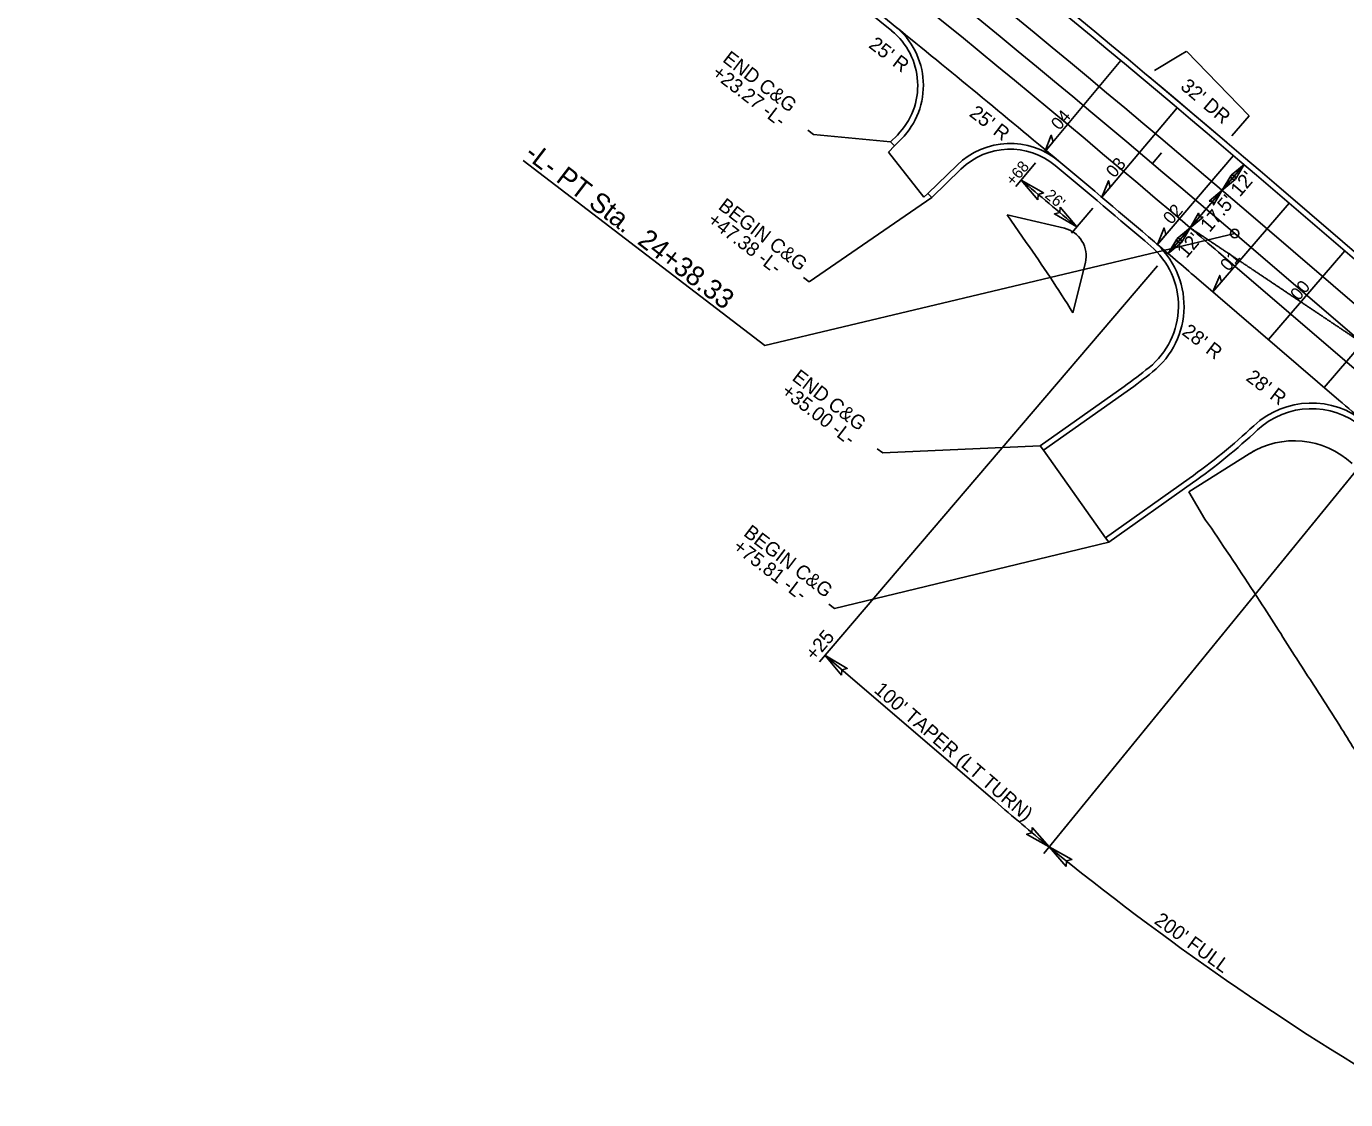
# Model space of a CAD drawing. Extents: x 1616561 to 1622460, y 896726 to 899651.
# Drawn here: x 1618799.1 to 1619267.2, y 897970.3 to 898351.2 of the extents above; entities that cross this region are included whole.
import ezdxf

# ---------------------------------------------------------------- set-up
doc = ezdxf.new("R2010")
doc.units = 0
for name, color, linetype in [('Old_Level_3', 7, 'Continuous'), ('Prop Conc Drive Radius Type', 7, 'Continuous'), ('Prop Dimension', 7, 'Continuous'), ('Prop DSN Text', 7, 'Continuous'), ('Prop Horizontal Alignment Tick Small', 7, 'Continuous'), ('Prop North Arrow NAD83 for Plan Sheets CELL', 7, 'Continuous'), ('Prop Rem of Exist Asph Pvmt', 7, 'Continuous'), ('Prop Superelevation  Arrow CELL', 7, 'Continuous'), ('Prop Terminator CELL', 7, 'Continuous'), ('Sheet Cutting Line CELL', 7, 'Continuous'), ('Sheet North Arrow CELL', 7, 'Continuous'), ('Sheet Sticker Preliminary CELL', 7, 'Continuous')]:
    doc.layers.add(name, color=color, linetype=linetype)

msp = doc.modelspace()

# ---------------------------------------------------------------- linework, layer by layer
at = {"layer": 'Old_Level_3'}
for p, q in [((1619233.52, 898284.32), (1619284.05, 898240.93)), ((1619222.12, 898271.04), (1619272.65, 898227.65)), ((1619214.3, 898261.93), (1619264.83, 898218.55))]:
    msp.add_line(p, q, dxfattribs=at)
for centre, radius, start, end in [((1615970.53, 894484.25), 5008.75, 49.34838, 55.47944), ((1615970.53, 894484.25), 4991.25, 49.50113, 55.47944), ((1615970.53, 894484.25), 4979.25, 50.08506, 50.95117), ((1615970.53, 894484.25), 4991.25, 49.34838, 49.50113), ((1615970.53, 894484.25), 4979.25, 49.34838, 49.57531), ((1619799.51, 898841.24), 820.75, 229.34838, 230.21163)]:
    msp.add_arc(centre, radius, start, end, dxfattribs=at)
for points in [[(1619253.85, 898251.7), (1619253.29, 898252.08), (1619252.72, 898252.46), (1619252.16, 898252.84), (1619251.59, 898253.22), (1619251.03, 898253.59), (1619250.46, 898253.97), (1619249.89, 898254.35), (1619249.33, 898254.73), (1619248.76, 898255.11), (1619248.2, 898255.49), (1619247.63, 898255.87), (1619247.07, 898256.24), (1619246.5, 898256.62), (1619245.94, 898257), (1619245.37, 898257.38), (1619244.81, 898257.76), (1619244.24, 898258.14), (1619243.67, 898258.52), (1619243.11, 898258.9), (1619242.54, 898259.27), (1619241.98, 898259.65), (1619241.41, 898260.03), (1619240.85, 898260.41), (1619240.28, 898260.79), (1619239.72, 898261.17), (1619239.15, 898261.55), (1619238.59, 898261.92), (1619238.02, 898262.3), (1619237.45, 898262.68), (1619236.89, 898263.06), (1619236.32, 898263.44), (1619235.76, 898263.82), (1619235.19, 898264.2), (1619234.63, 898264.58), (1619234.06, 898264.95), (1619233.5, 898265.33), (1619232.93, 898265.71), (1619232.37, 898266.09), (1619231.8, 898266.47), (1619231.23, 898266.85), (1619230.67, 898267.23), (1619230.1, 898267.6), (1619229.54, 898267.98), (1619228.97, 898268.36), (1619228.41, 898268.74), (1619227.84, 898269.12), (1619227.28, 898269.5), (1619226.71, 898269.88), (1619226.15, 898270.26), (1619225.58, 898270.63), (1619225.01, 898271.01), (1619224.45, 898271.39), (1619223.88, 898271.77), (1619223.32, 898272.15), (1619222.75, 898272.53), (1619222.19, 898272.9), (1619221.62, 898273.28), (1619221.06, 898273.66), (1619220.49, 898274.04), (1619219.93, 898274.42), (1619219.36, 898274.79), (1619218.8, 898275.17), (1619218.23, 898275.55), (1619217.67, 898275.93), (1619217.1, 898276.3), (1619216.54, 898276.68), (1619215.97, 898277.06), (1619215.41, 898277.43), (1619214.84, 898277.81), (1619214.28, 898278.19), (1619213.71, 898278.56), (1619213.15, 898278.94), (1619212.58, 898279.32), (1619212.02, 898279.69)], [(1619295.8, 898223.93), (1619294.65, 898224.65), (1619294.08, 898225.02), (1619293.51, 898225.38), (1619292.94, 898225.74), (1619292.36, 898226.11), (1619291.79, 898226.48), (1619291.22, 898226.84), (1619290.65, 898227.21), (1619290.08, 898227.58), (1619289.51, 898227.95), (1619288.94, 898228.31), (1619288.37, 898228.68), (1619287.8, 898229.05), (1619287.23, 898229.42), (1619286.67, 898229.79), (1619286.1, 898230.17), (1619285.53, 898230.54), (1619284.96, 898230.91), (1619284.39, 898231.28), (1619283.83, 898231.66), (1619283.26, 898232.03), (1619282.69, 898232.4), (1619282.13, 898232.78), (1619281.56, 898233.15), (1619280.99, 898233.53), (1619280.43, 898233.91), (1619279.86, 898234.28), (1619279.3, 898234.66), (1619278.73, 898235.04), (1619278.17, 898235.42), (1619277.6, 898235.8), (1619277.04, 898236.18), (1619276.47, 898236.55), (1619275.9, 898236.93), (1619275.34, 898237.31), (1619274.77, 898237.69), (1619274.21, 898238.07), (1619273.64, 898238.45), (1619273.08, 898238.83), (1619272.51, 898239.21), (1619271.95, 898239.58), (1619271.38, 898239.96), (1619270.82, 898240.34), (1619270.25, 898240.72), (1619269.68, 898241.1), (1619269.12, 898241.48), (1619268.55, 898241.86), (1619267.99, 898242.23), (1619267.42, 898242.61), (1619266.86, 898242.99), (1619266.29, 898243.37), (1619265.73, 898243.75), (1619265.16, 898244.13), (1619264.6, 898244.51), (1619264.03, 898244.89), (1619263.46, 898245.26), (1619262.9, 898245.64), (1619262.33, 898246.02), (1619261.77, 898246.4), (1619261.2, 898246.78), (1619260.64, 898247.16), (1619260.07, 898247.54), (1619259.51, 898247.91), (1619258.94, 898248.29), (1619258.38, 898248.67), (1619257.81, 898249.05), (1619257.25, 898249.43), (1619256.68, 898249.81), (1619256.11, 898250.19), (1619255.55, 898250.57), (1619254.98, 898250.94), (1619254.42, 898251.32), (1619253.85, 898251.7)]]:
    msp.add_spline(points, degree=3, dxfattribs=at)
at = {"layer": 'Prop Conc Drive Radius Type'}
msp.add_line((1619197.42, 898333.28), (1619224.94, 898310.04), dxfattribs=at)
at = {"layer": 'Prop Dimension'}
for p, q in [((1619231.17, 898302.13), (1619223.38, 898293)), ((1619223.38, 898293), (1619212.02, 898279.69)), ((1619212.02, 898279.69), (1619204.22, 898270.57)), ((1619200.49, 898266.2), (1619080.5, 898125.7)), ((1619277.46, 898201.46), (1619160.12, 898057.65)), ((1619082.45, 898127.98), (1619142.66, 898076.28))]:
    msp.add_line(p, q, dxfattribs=at)
for centre, radius, start, end in [((1619801.94, 898839.21), 1008.32, 229.16856, 230.60636), ((1619799.51, 898841.24), 1008.36, 230.78618, 239.73865)]:
    msp.add_arc(centre, radius, start, end, dxfattribs=at)
at = {"layer": 'Prop DSN Text'}
for p, q in [((1619076.37, 898314.34), (1619078.35, 898312.83)), ((1619105.73, 898310.21), (1619078.35, 898312.83)), ((1619120.39, 898290.5), (1619076.8, 898260.56)), ((1619074.82, 898262.08), (1619076.8, 898260.56)), ((1619101.01, 898201.31), (1619102.99, 898199.79)), ((1619158.85, 898202.36), (1619102.99, 898199.79)), ((1619183.12, 898168.08), (1619085.79, 898144.64)), ((1619083.81, 898146.15), (1619085.79, 898144.64))]:
    msp.add_line(p, q, dxfattribs=at)
at = {"layer": 'Prop Horizontal Alignment Tick Small'}
for p, q in [((1619105.73, 898310.21), (1619108.13, 898312.63)), ((1619105.73, 898310.21), (1619107.16, 898308.8)), ((1619120.39, 898290.5), (1619130.71, 898300.54)), ((1619242.64, 898294.94), (1619293.17, 898251.55)), ((1619120.39, 898290.5), (1619118.99, 898291.93)), ((1619158.85, 898202.36), (1619188.56, 898223.41)), ((1619158.85, 898202.36), (1619160, 898200.73)), ((1619183.12, 898168.08), (1619212.84, 898189.13)), ((1619183.12, 898168.08), (1619181.97, 898169.72))]:
    msp.add_line(p, q, dxfattribs=at)
for centre, radius, start, end in [((1615970.53, 894484.25), 5022.75, 49.34838, 54.94423), ((1615970.53, 894484.25), 4977.25, 50.95117, 54.94423), ((1619090.36, 898330.22), 25, 315.2913, 50.9512), ((1619148.14, 898282.62), 25, 50.0851, 134.2061), ((1615970.53, 894484.25), 4977.25, 49.57531, 50.08506), ((1619179.86, 898251.91), 28, 308.8694, 49.5753), ((1619085.1, 898369.48), 179, 305.3092, 308.8694), ((1619255.07, 898187.51), 28, 50.2116, 133.0475), ((1619085.1, 898369.48), 221, 305.3092, 313.0475)]:
    msp.add_arc(centre, radius, start, end, dxfattribs=at)
at = {"layer": 'Prop North Arrow NAD83 for Plan Sheets CELL'}
for points in [[(1619160.42, 898306.67), (1619162.73, 898312.55), (1619163.38, 898310.22)], [(1619180.69, 898290.54), (1619183.02, 898296.42), (1619183.67, 898294.08)], [(1619200.43, 898273.8), (1619202.8, 898279.66), (1619203.43, 898277.32)], [(1619220.12, 898256.94), (1619222.52, 898262.79), (1619223.14, 898260.45)]]:
    msp.add_lwpolyline(points, close=True, dxfattribs=at)
at = {"layer": 'Prop Rem of Exist Asph Pvmt'}
for p, q in [((1619147.07, 898284.27), (1619167.39, 898279.52)), ((1619153.89, 898274.54), (1619147.07, 898284.27)), ((1619174.83, 898267.4), (1619170.44, 898249.53)), ((1619211.53, 898185.98), (1619232.98, 898199.49)), ((1619217.27, 898176.32), (1619211.53, 898185.98)), ((1619217.49, 898175.99), (1619217.27, 898176.32)), ((1619219.57, 898173.07), (1619217.49, 898175.99))]:
    msp.add_line(p, q, dxfattribs=at)
for centre, radius, start, end in [((1619165.12, 898269.78), 10, 346.1921, 76.855), ((1619248.97, 898174.11), 30, 46.8949, 122.2079), ((1619248.97, 898174.11), 30, 116.3811, 122.2079)]:
    msp.add_arc(centre, radius, start, end, dxfattribs=at)
msp.add_ellipse((1618704.9, 897963.19), major_axis=(-406.38, 374.84), ratio=0.987706, start_param=4.441274, end_param=4.495551, dxfattribs=at)
msp.add_spline([(1619275.41, 898086.22), (1619265.12, 898102.96), (1619249.89, 898126.67), (1619236.73, 898147.21), (1619219.57, 898173.07)], degree=3, dxfattribs=at)
at = {"layer": 'Prop Superelevation  Arrow CELL'}
msp.add_line((1619198.65, 898302.54), (1619201.88, 898306.35), dxfattribs=at)
at = {"layer": 'Prop Terminator CELL'}
for p, q in [((1619208.62, 898341.05), (1619199.36, 898335.57)), ((1619208.62, 898341.05), (1619210.61, 898342.27)), ((1619210.77, 898342.37), (1619232.91, 898319.43)), ((1619232.91, 898319.43), (1619226.86, 898312.35)), ((1619104.93, 898306.56), (1619107.16, 898308.8)), ((1619107.16, 898308.8), (1619109.55, 898311.22)), ((1619104.93, 898306.56), (1619117.57, 898290.54)), ((1619118.99, 898291.93), (1619129.32, 898301.97)), ((1619241.34, 898293.42), (1619291.86, 898250.04)), ((1619117.57, 898290.54), (1619118.99, 898291.93)), ((1619160, 898200.73), (1619189.72, 898221.77)), ((1619160, 898200.73), (1619181.97, 898169.72)), ((1619181.97, 898169.72), (1619211.68, 898190.77))]:
    msp.add_line(p, q, dxfattribs=at)
for points in [[(1619227.95, 898296.79), (1619223.38, 898293), (1619226.41, 898298.15), (1619226.72, 898296.91)], [(1619226.61, 898298.33), (1619231.17, 898302.13), (1619228.14, 898296.98), (1619227.84, 898298.22)], [(1619157.96, 898289.67), (1619152.04, 898296.63), (1619160.01, 898292.06), (1619158.11, 898291.57)], [(1619218.82, 898289.21), (1619223.38, 898293), (1619220.35, 898287.85), (1619220.05, 898289.1)], [(1619165.94, 898287.02), (1619171.82, 898280.03), (1619163.87, 898284.65), (1619165.78, 898285.13)], [(1619216.58, 898283.49), (1619212.02, 898279.69), (1619215.04, 898284.84), (1619215.35, 898283.6)], [(1619207.45, 898275.9), (1619212.02, 898279.69), (1619208.99, 898274.54), (1619208.68, 898275.79)], [(1619208.79, 898274.36), (1619204.22, 898270.57), (1619207.25, 898275.72), (1619207.56, 898274.47)], [(1619088.27, 898120.94), (1619082.45, 898127.98), (1619090.36, 898123.3), (1619088.44, 898122.84)], [(1619156.02, 898066.87), (1619162.01, 898059.97), (1619153.99, 898064.46), (1619155.89, 898064.97)], [(1619168.01, 898053.08), (1619162.01, 898059.97), (1619170.04, 898055.49), (1619168.14, 898054.98)]]:
    msp.add_lwpolyline(points, close=True, dxfattribs=at)
for centre, radius, start, end in [((1615970.53, 894484.25), 5020.75, 49.34838, 54.94423), ((1615970.53, 894484.25), 4979.25, 50.95117, 54.94423), ((1619090.36, 898330.22), 27, 315.2913, 50.9512), ((1619148.14, 898282.62), 27, 50.0851, 134.2061), ((1615970.53, 894484.25), 4979.25, 49.57531, 50.08506), ((1619179.86, 898251.91), 30, 308.8694, 49.5753), ((1619085.1, 898369.48), 181, 305.3092, 308.8694), ((1619255.07, 898187.51), 30, 50.2116, 133.0475), ((1619085.1, 898369.48), 219, 305.3092, 313.0475)]:
    msp.add_arc(centre, radius, start, end, dxfattribs=at)
at = {"layer": 'Sheet Cutting Line CELL'}
msp.add_line((1619227.82, 898277.68), (1619278.35, 898234.29), dxfattribs=at)
msp.add_arc((1615970.53, 894484.25), 5000, 49.34838, 55.47944, dxfattribs=at)
at = {"layer": 'Sheet North Arrow CELL'}
for p, q in [((1619061.07, 898237.95), (1618975.32, 898303.62)), ((1619227.82, 898277.68), (1619061.07, 898237.95))]:
    msp.add_line(p, q, dxfattribs=at)
msp.add_circle((1619227.82, 898277.68), 1.5, dxfattribs=at)
at = {"layer": 'Sheet Sticker Preliminary CELL'}
for p, q in [((1619160.85, 898307.19), (1619187.44, 898339.05)), ((1619180.69, 898290.54), (1619207.44, 898322.27)), ((1619150.12, 898294.33), (1619157.18, 898302.79)), ((1619200.43, 898273.8), (1619227.35, 898305.38)), ((1619169.89, 898277.74), (1619177.46, 898286.72)), ((1619220.12, 898256.94), (1619247.16, 898288.42)), ((1619239.85, 898240), (1619266.89, 898271.48)), ((1619259.58, 898223.06), (1619286.61, 898254.55))]:
    msp.add_line(p, q, dxfattribs=at)
msp.add_arc((1615970.53, 894484.25), 4965.5, 49.85636, 50.1543, dxfattribs=at)

# ---------------------------------------------------------------- texts
at = {"layer": 'Prop Dimension'}
for s, rotation, p in [("25' R", 322.554, (1619097.62, 898343.95)), ("32' DR", 319.6719, (1619208.23, 898329.3)), ("25' R", 322.554, (1619133.32, 898319.63)), ("12'", 49.5011, (1619229.67, 898290.41)), ("17.5'", 49.5011, (1619218.92, 898277.83)), ("12'", 49.5011, (1619210.71, 898268.62)), ("28' R", 322.554, (1619208.76, 898242.06)), ("28' R", 322.554, (1619231.5, 898225.82)), ('+25', 49.5011, (1619078.75, 898125.71)), ("100' TAPER (LT TURN)", 319.3484, (1619099.53, 898115.14)), ("200' FULL", 323.9053, (1619198.95, 898033.06))]:
    msp.add_text(s, height=5, rotation=rotation, dxfattribs=at).set_placement(p)
at = {"layer": 'Prop DSN Text'}
for s, p in [('END C&G', (1619045.8, 898338.9)), ('+23.27 -L-', (1619041.95, 898333.87)), ('BEGIN C&G', (1619044.25, 898286.64)), ('+47.38 -L-', (1619040.4, 898281.61)), ('END C&G', (1619070.44, 898225.87)), ('+35.00 -L-', (1619066.59, 898220.84)), ('BEGIN C&G', (1619053.24, 898170.71)), ('+75.81 -L-', (1619049.39, 898165.68))]:
    msp.add_text(s, height=5, rotation=322.554, dxfattribs=at).set_placement(p)
at = {"layer": 'Sheet North Arrow CELL'}
msp.add_text('-L- PT Sta.  24+38.33', height=7, rotation=322.554, dxfattribs=at).set_placement((1618975.47, 898304.96))
at = {"layer": 'Sheet Sticker Preliminary CELL'}
for s, height, rotation, p in [('04', 4.5, 49.3484, (1619165.62, 898314.04)), ('+68', 4, 49.9905, (1619149.3, 898294.37)), ('03', 4.5, 49.3484, (1619185.14, 898297.14)), ("26'", 4, 319.9905, (1619160.19, 898290.73)), ('02', 4.5, 49.3484, (1619205.38, 898280.61)), ('01', 4.5, 49.3484, (1619225.65, 898263.99)), ('00', 4.5, 49.3484, (1619250.53, 898253.55))]:
    msp.add_text(s, height=height, rotation=rotation, dxfattribs=at).set_placement(p)

doc.saveas('drawing.dxf')
